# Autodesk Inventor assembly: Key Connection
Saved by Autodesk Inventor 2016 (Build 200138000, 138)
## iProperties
Created: 2015-03
Part Number: Key Connection
Document SubType Name: Assembly
Designer: Uglješa
ClientObjectVersion: 1
Author: Uglješa
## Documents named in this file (1)
- C:\Users\Ugljesa\Desktop\Turbokompr\Assembly1\Design Accelerator\Key Connection7.iam
